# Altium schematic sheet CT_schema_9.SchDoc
size 277 x 170 mm
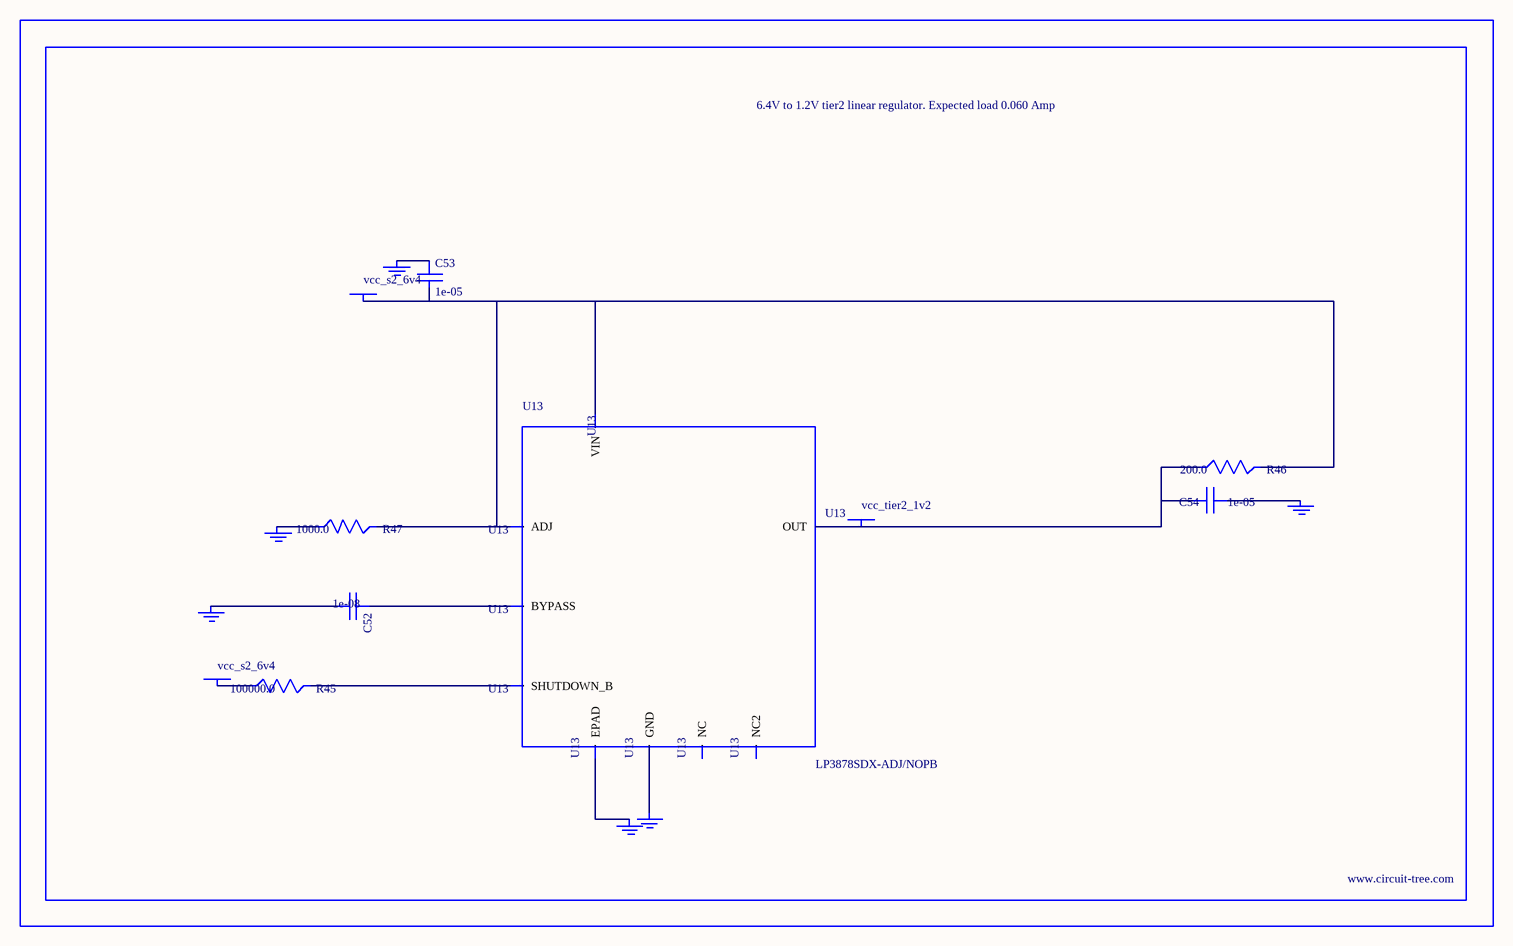
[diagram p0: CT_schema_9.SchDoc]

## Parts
BORDER8  (no value)
C52  1e-08  [C0402]
C53  1e-05  [C1206]
C54  1e-05  [C0805]
GND_INSTANCE_8_0  (no value)
GND_INSTANCE_8_1  (no value)
GND_INSTANCE_8_2  (no value)
GND_INSTANCE_8_3  (no value)
GND_INSTANCE_8_4  (no value)
GND_INSTANCE_8_5  (no value)
POWER_INSTANCE_8_0  vcc_s2_6v4
POWER_INSTANCE_8_1  vcc_s2_6v4
POWER_INSTANCE_8_2  vcc_tier2_1v2
R45  100000.0  [R0603]
R46  200.0  [R0603]
R47  1000.0  [R0603]
U13  LP3878SDX-ADJ/NOPB  [WSON-8]

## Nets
NetC52_1: C52.1 U13.1(BYPASS)
NetC52_2: C52.2 GND_INSTANCE_8_0.0(GND)
NetC53_1: C53.1 GND_INSTANCE_8_1.0(GND)
NetC53_2: C53.2 POWER_INSTANCE_8_0.0(PWR) R46.2 R47.2 U13.4(VIN) U13.6(ADJ)
NetC54_1: C54.1 GND_INSTANCE_8_2.0(GND)
NetC54_2: C54.2 POWER_INSTANCE_8_2.0(PWR) R46.1 U13.5(OUT)
NetGND_INSTANCE_8_3_0: GND_INSTANCE_8_3.0(GND) R47.1
NetGND_INSTANCE_8_4_0: GND_INSTANCE_8_4.0(GND) U13.PAD(EPAD)
NetGND_INSTANCE_8_5_0: GND_INSTANCE_8_5.0(GND) U13.3(GND)
NetPOWER_INSTANCE_8_1_0: POWER_INSTANCE_8_1.0(PWR) R45.1
NetR45_2: R45.2 U13.8(SHUTDOWN_B)

Not connected (* = marked no-connect by the designer): U13 2(NC) 7(NC2)

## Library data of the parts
BORDER8 = BORDER_PAGE8
C52 = C0402C103K3RAC
C53 = C1206C106K3RACTU
C54 = GRM219R60J106ME19D
GND_INSTANCE_8_0-GND_INSTANCE_8_5 = GND
POWER_INSTANCE_8_0-POWER_INSTANCE_8_2 = PWR
R45 = RC0603JR-07100KL
R46 = RC0603JR-07200RL
R47 = RC0603JR-071KL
